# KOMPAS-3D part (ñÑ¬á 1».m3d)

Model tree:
1. Эскиз:1
2. Операция выдавливания:1
     Расстояние 1 = 0.6
3. Эскиз:2
4. Вырезать элемент выдавливания:1
     Толщина стенки 1 = 3; Толщина стенки 2 = 3; Расстояние 1 = 10
5. Эскиз:3
6. Вырезать элемент выдавливания:2
     Толщина стенки 1 = 3; Толщина стенки 2 = 3; Расстояние 1 = 10
7. Эскиз:4
8. Вырезать элемент выдавливания:3
     Толщина стенки 1 = 3; Толщина стенки 2 = 3; Расстояние 1 = 10
9. Эскиз:5
10. Вырезать элемент выдавливания:4
     Толщина стенки 1 = 3; Толщина стенки 2 = 3; Расстояние 1 = 10
